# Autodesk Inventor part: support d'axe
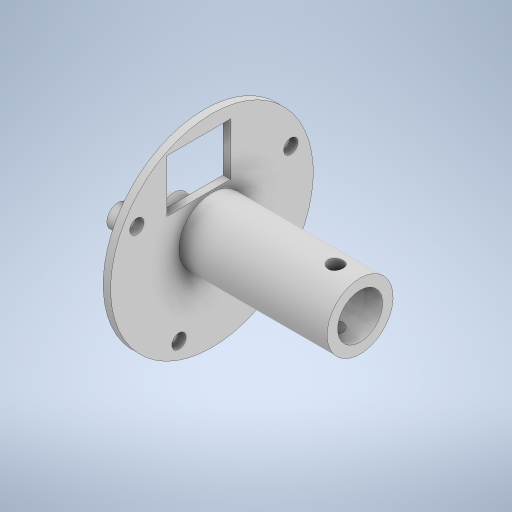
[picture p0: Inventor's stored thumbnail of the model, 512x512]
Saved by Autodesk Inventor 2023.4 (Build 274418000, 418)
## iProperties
Created: 2024-03
Part Number: support d'axe
Material: Générique
Document SubType Name: Modeling
Designer: mel
Density: 1 g/cm^3
Appearance: Par défaut
Author: mel
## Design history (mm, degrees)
sketch "Esquisse1"
  geometry: L1 (0, 0)-(2, 0); L2 (2, 8.8)-(2, 27); L3 (2, 27)-(0, 27); L4 (2, 0)-(41.5, 0); L5 (41.5, 0)-(41.5, 8.8); L6 (41.5, 8.8)-(2, 8.8); L7 (0, 0)-(-8, 0); L8 (-8, 3.875)-(0, 3.875); L9 (-8, 0)-(-14, 0); L10 (-14, 0)-(-14, 2.5); L11 (-14, 2.5)-(-8, 2.5); L12 (-8, 1.5)-(-8, 0); L13 (-14, 0)-(-8, 0); L14 (-8, 0)-(-8, 1.5); L15 (-8, 1.5)-(-14, 1.5); L16 (-14, 1.5)-(-14, 0); L17 (0, 0)-(-7, 0); L18 (-7, 1.5)-(-7, 2.875); L19 (-7, 2.875)-(0, 2.875); L20 (41.5, 0)-(-3.984, 0); L21 (1, 2.875)-(1, 6); L22 (1, 6)-(41.5, 6); L23 (41.5, 6)-(41.5, 0); L24 (0, 27)-(0, 3.875); L25 (-8, 0)-(-8, 1.5); L26 (-8, 2.5)-(-8, 3.875); L27 (-8, 1.5)-(-7, 1.5); L28 (0, 2.875)-(1, 2.875); L29 (0, 2.875)-(0, 2.5); L30 (0, 1.5)-(0, 0); L31 (0, 2.875)-(0, 2.5); L32 (0, 1.5)-(0, 0); L33 (0, 2.875)-(0, 2.5); L34 (0, 1.5)-(0, 0); 2 further points
  constraints: 68 end point, 19 parallel, 9 perpendicular, 8 horizontal, 2 point on line
  dimensions: "d0" = 2 distance of L3.end L2.end; "d1" = 27 distance of L2.end L1.end; "d2" = 8.8 distance of L5.end L4.end; "d3" = 39.5 distance between parallel lines of L5 L2; "d4" = 8 distance of L8.start L8.end; "d5" = 3.875 distance of L7.end L8.start; "d6" = 6 distance of L10.end L11.end; "d7" = 2.5 distance of L9.end L10.end; "d8" = 1.5 distance of L12.start L13.end; "d9" = 7 distance of L19.end L18.end; "d10" = 2.875 distance of L17.end L18.end; "d11" = 40.5 distance of L21.end L22.end; "d12" = 7.8 distance of L20.end L21.end; "d13" = 6 distance between parallel lines of L22 L4
revolve "Révolution1" sketch "Esquisse1" stored, may be unused: angle "d14" = 90 deg
sketch "Esquisse2"
  geometry: L1 (-12, 23.3)-(5, 23.3); L2 (5, 23.3)-(5, 9.3); L3 (5, 9.3)-(-12, 9.3); L4 (-12, 9.3)-(-12, 23.3); C1 r 27 at (0, 0) reference; 1 further point
  constraints: 8 end point, 2 parallel, 1 horizontal, 1 perpendicular
  dimensions: "d15" = 17 distance of L2.end L3.end; "d16" = 14 distance of L1.end L2.end; "d17" = 3.7 distance edge to line of C1 L1; "d18" = 15 distance edge to line of C1 L4
extrude "Extrusion1" cut sketch "Esquisse2" distance "d19" = 10; taper "d20" = 0 deg
sketch "Esquisse3"
  geometry: L1 (0, 0)-(-21.003, 9); L2 (0, 0)-(20.028, 11); L3 (0, 0)-(8.793, -21.09); L4 (-19.369, 8.3)-(-2.91, 1.247); L5 (-2.91, 1.247)-(-3.146, 0.695); L6 (-3.146, 0.695)-(-19.605, 7.748); L7 (-19.605, 7.748)-(-19.369, 8.3); L8 (-19.369, 8.3)-(-2.91, 1.247); L9 (-2.91, 1.247)-(-2.674, 1.798); L10 (-2.674, 1.798)-(-19.133, 8.851); L11 (-19.133, 8.851)-(-19.369, 8.3); L12 (17.917, 9.84)-(3.023, 1.66); L13 (3.023, 1.66)-(2.734, 2.186); L14 (2.734, 2.186)-(17.628, 10.366); L15 (17.628, 10.366)-(17.917, 9.84); L16 (17.917, 9.84)-(3.023, 1.66); L17 (3.023, 1.66)-(3.312, 1.134); L18 (3.312, 1.134)-(18.205, 9.314); L19 (18.205, 9.314)-(17.917, 9.84); L20 (1.5, -3.598)-(7.965, -19.104); L21 (7.965, -19.104)-(8.519, -18.873); L22 (8.519, -18.873)-(2.054, -3.367); L23 (8.793, -21.09)-(1.5, -3.598); L24 (0.946, -3.829)-(8.24, -21.321); L25 (8.24, -21.321)-(8.793, -21.09); L26 (0.946, -3.829)-(0.763, -3.388); L27 (0.763, -3.388)-(1.87, -2.927); L28 (1.87, -2.927)-(2.054, -3.367); C1 r 3 at (-21.003, 9); C2 r 3 at (20.028, 11); C3 r 3 at (8.793, -21.09); C4 r 2.5 at (0, 0) reference; C5 r 1.5 at (0, 0) reference; A1 r 22.85 centre (0, 0) between (-21.003, 9) and (20.028, 11); 10 further points
  constraints: 56 end point, 12 parallel, 6 point on line, 5 perpendicular, 4 centre point, 4 point on circle, 2 collinear, 1 coincident
  dimensions: "d21" = 45.7 diameter of A1; "d22" = 9 vertical distance of point (0, 0) L1.end; "d23" = 11 vertical distance of C2.centre point (0, 0); "d24" = 34 distance of L3.end C2.centre; "d25" = 42.34672 distance of L3.end L1.end (derived); "d26" = 6 diameter of C1; "d27" = 6 diameter of C2; "d28" = 6 diameter of C3; "d29" = 0.6 distance of L4.end L5.end; "d30" = 0.6 distance of L9.end L4.end; "d31" = 0.6 distance of L12.end L13.end; "d32" = 0.6 distance of L17.end L12.end; "d33" = 0.6 distance of L21.end L20.end; "d34" = 0.6 distance of L24.start L20.start
extrude "Extrusion2" join sketch "Esquisse3" distance "d35" = 3; taper "d36" = 0 deg
sketch "Esquisse4"
  geometry: L1 (0, 0)-(3, 0) reference; L2 (0, -16.082)-(0, 0) reference; L3 (3, -16.082)-(0, -16.082) reference; L4 (3, 0)-(3, -16.082) reference; L5 (0, 2.656)-(-0.5, 2.656); L6 (-0.5, 2.656)-(-0.5, -8.5); L7 (0, -9.511)-(0, 2.656); L8 (0, -9.511)-(0, -10.5); L9 (0, 0)-(0, -16.082) reference; L10 (-0.5, -8.5)-(0, -10.5); L11 (0, -0.047)-(-5, -0.047) reference; L12 (0, 0)-(3, 0) reference; L13 (-0.5, 0)-(0, 0); 3 further points
  constraints: 12 end point, 3 point on line, 2 parallel, 1 horizontal, 1 perpendicular
  dimensions: "d38" = 10.5 distance from line of L8.end L13; "d39" = 8.5 distance of L6.end L13.start; "d40" = 0.5 distance between parallel lines of L2 L6
extrude "Extrusion3" join sketch "Esquisse4" stored distance "d41" = 3; taper "d42" = 0 deg
sketch "Esquisse5"
  geometry: 1 further point
sketch "Esquisse6"
  geometry: L1 (0, 0)-(3, 0) reference; L2 (0, -16.082)-(0, 0) reference; L3 (3, -16.082)-(0, -16.082) reference; L4 (3, 0)-(3, -16.082) reference; L5 (0, -16.082)-(0, 0) reference; L6 (-0.5, -8.5)-(-0.5, 1.821); L7 (-0.5, 1.821)-(0, 1.821); L8 (0, 1.821)-(0, -10.5); L9 (0, -10.5)-(-0.5, -8.5); L10 (-5, 7.703)-(-5, -0.047) reference; L11 (3, 6.992)-(-0.5, 6.992) reference; L12 (-0.5, 6.992)-(-0.5, 6.156) reference; L13 (-0.5, 6.156)-(3, 6.156) reference; L14 (3, 6.156)-(3, 0) reference; L15 (3, 0)-(0, 0) reference; L16 (0, 0)-(0, 0) reference; L17 (0, 0)-(3, 0) reference; L18 (3, 0)-(3, 3.641) reference; L19 (3, 3.641)-(0, 3.641) reference; L20 (0, 3.641)-(0, 4.835) reference; L21 (0, 4.835)-(3, 4.835) reference; L22 (3, 4.835)-(3, 6.992) reference; 3 further points
  constraints: 8 end point, 1 parallel, 1 point on line
  dimensions: "d43" = 10.5 distance of L8.end L1.start; "d44" = 8.5 vertical distance of L6.start L1.start; "d45" = 0.5 distance between parallel lines of L6 L2
extrude "Extrusion4" join sketch "Esquisse6" stored distance "d46" = 3; taper "d47" = 0 deg
sketch "Esquisse7"
  geometry: L1 (0, 0)-(0, 16.082) reference; L2 (-0.5, 8.5)-(-0.5, -1.023); L3 (-0.5, -1.023)-(0, -1.023); L4 (0, -1.023)-(0, 10.5); L5 (0, 10.5)-(-0.5, 8.5); 2 further points
  constraints: 8 end point, 1 parallel, 1 point on line
  dimensions: "d48" = 0.5 distance between parallel lines of L2 L1; "d49" = 10.5 distance of L1.start L4.end; "d50" = 8.5 vertical distance of L1.start L2.start
extrude "Extrusion5" join sketch "Esquisse7" stored distance "d51" = 10; taper "d52" = 0 deg
sketch "Esquisse8"
  geometry: A1 r 3 centre (-21.003, 9) between (-18.065, 8.394) and (-18.537, 7.291) reference; A2 r 3 centre (20.028, 11) between (17.741, 9.059) and (17.163, 10.111) reference; A3 r 3 centre (8.793, -21.09) between (7.108, -18.608) and (8.216, -18.146) reference; 1 further point
hole "Perçage1" sketch "Esquisse8" at (-21.003, 9), (20.028, 11), (8.793, -21.09) diameter "d53" = 2; stored, may be unused: countersink angle "d57" = 90 deg, drill point angle "d59" = 118 deg; dims "d54" = 6, "d55" = 4, "d56" = 2, "d58" = 18
sketch "Esquisse9"
  geometry: L1 (5, 23.3)-(5, 9.3) reference; L2 (5, 9.3)-(-12, 9.3) reference; L3 (-12, 9.3)-(-12, 23.3) reference; L4 (-12, 23.3)-(5, 23.3) reference; C1 r 1 at (-20.028, 11) reference; C2 r 1 at (21.003, 9) reference; C3 r 1 at (-8.793, -21.09) reference; C4 r 27 at (0, 0) reference; C5 r 8.8 at (0, 0) reference; 1 further point
hole "Perçage2" sketch "Esquisse9" at (-20.028, 11), (-8.793, -21.09), (21.003, 9) diameter "d60" = 3.8; stored, may be unused: countersink angle "d64" = 90 deg, drill point angle "d66" = 0 deg; dims "d61" = 6, "d62" = 4, "d63" = 2, "d65" = 2.08
node "Plan de construction1"
sketch "Esquisse10"
  geometry: L1 (19.75, -8.8)-(19.75, 8.8) reference; L2 (19.75, 2.25)-(-2, 2.25); L3 (-2, -2.25)-(19.75, -2.25); L4 (19.75, -2.25)-(19.75, 2.25); A1 r 2.25 centre (-2, 0) between (-2, 2.25) and (-2, -2.25); 4 further points
  constraints: 6 end point, 2 midpoint, 2 point on circle, 2 tangent, 1 centre point, 1 horizontal, 1 parallel, 1 point on line
  dimensions: "d67" = 2.25 distance from line of L2 point (19.75, 0); "d68" = 2.25 distance from line of point (19.75, 0) L3
extrude "Extrusion6" join sketch "Esquisse10" distance "d70" = 1; taper "d72" = 0 deg; dims "d71" = 1, "d73" = 0
sketch "Esquisse11"
  geometry: L1 (-2, -27)-(-2, 27) reference; L2 (-2, 27)-(-65.921, 27); L3 (-65.921, 27)-(-65.921, 9.8); L4 (-65.921, 9.8)-(-2, 9.8); L5 (-2, 9.8)-(-2, 27); L6 (-41.5, 8.8)-(-2, 8.8) reference; L7 (29.984, 0)-(-81.906, 0) reference; 2 further points
  constraints: 8 end point, 2 parallel, 1 horizontal, 1 perpendicular
  dimensions: "d74" = 1 distance between parallel lines of L4 L6
revolve "Révolution2" sketch "Esquisse11" stored, may be unused: angle "d75" = 90 deg
sketch "Esquisse12"
  geometry: L1 (-41.5, -6)-(-41.5, 6) reference; C1 r 2 at (-35, 0); 1 further point
  constraints: 1 centre point
  dimensions: "d76" = 4 diameter of C1; "d77" = 4.5 distance edge to line of C1 L1
extrude "Extrusion7" cut sketch "Esquisse12" extent not by distance; stored distance "d78" = 0; taper "d79" = 0 deg
node "Solide1"
node "Boucle projetée1"
node "Boucle projetée2"
node "Boucle projetée3"
node "Boucle projetée4"
